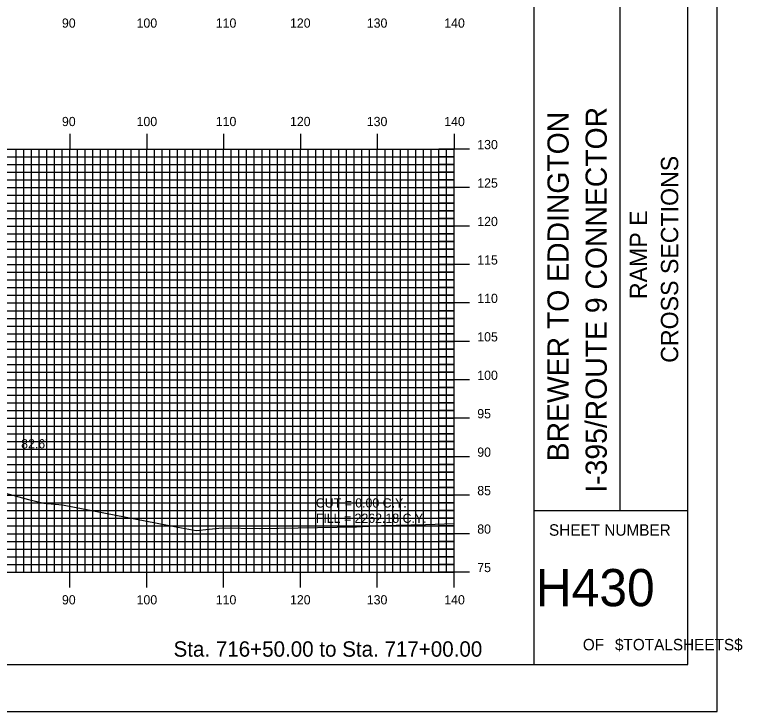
# Model space of a CAD drawing. Extents: x 856871 to 857214, y 364366 to 364586.
# Drawn here: x 857119.6 to 857214.3, y 364365.7 to 364456.3 of the extents above; entities that cross this region are included whole.
import ezdxf

# ---------------------------------------------------------------- set-up
doc = ezdxf.new("R2010")
doc.units = 0
for name, color, linetype in [('BORDER', 7, 'Continuous'), ('D_Text_Standard', 7, 'Continuous'), ('H_V ANNOTATION', 7, 'Continuous'), ('MAJOR', 7, 'Continuous'), ('MINOR', 7, 'Continuous'), ('PLOT BOUNDARY', 7, 'Continuous'), ('S_Roadway_Centerline', 7, 'Continuous')]:
    doc.layers.add(name, color=color, linetype=linetype)

msp = doc.modelspace()

# ---------------------------------------------------------------- linework, layer by layer
at = {"layer": 'BORDER'}
for p, q in [((857187.222, 364371.787), (857187.222, 364581.787)), ((857198.404, 364391.793), (857198.404, 364461.793)), ((857187.222, 364391.793), (857207.222, 364391.793))]:
    msp.add_line(p, q, dxfattribs=at)
msp.add_lwpolyline([(856887.222, 364371.787), (857207.222, 364371.787), (857207.222, 364581.787), (856887.222, 364581.787)], close=True, dxfattribs=at)
at = {"layer": 'MAJOR'}
for p, q in [((857126.822, 364440.791), (857126.822, 364438.787)), ((857136.822, 364440.791), (857136.822, 364438.787)), ((857146.822, 364440.791), (857146.822, 364438.787)), ((857156.822, 364440.791), (857156.822, 364438.787)), ((857166.822, 364440.791), (857166.822, 364438.787)), ((857176.822, 364440.791), (857176.822, 364438.787)), ((856896.822, 364438.787), (857176.822, 364438.787)), ((856896.822, 364438.787), (857176.822, 364438.787)), ((857126.822, 364383.787), (857126.822, 364438.787)), ((857136.822, 364383.787), (857136.822, 364438.787)), ((857146.822, 364383.787), (857146.822, 364438.787)), ((857156.822, 364383.787), (857156.822, 364438.787)), ((857166.822, 364383.787), (857166.822, 364438.787)), ((857178.826, 364438.787), (857174.818, 364438.787)), ((857176.822, 364383.787), (857176.822, 364438.787)), ((857176.822, 364383.787), (857176.822, 364438.787)), ((856896.822, 364433.787), (857176.822, 364433.787)), ((857178.826, 364433.787), (857174.818, 364433.787)), ((856896.822, 364428.787), (857176.822, 364428.787)), ((857178.826, 364428.787), (857174.818, 364428.787)), ((856896.822, 364423.787), (857176.822, 364423.787)), ((857178.826, 364423.787), (857174.818, 364423.787)), ((856896.822, 364418.787), (857176.822, 364418.787)), ((857178.826, 364418.787), (857174.818, 364418.787)), ((856896.822, 364413.787), (857176.822, 364413.787)), ((857178.826, 364413.787), (857174.818, 364413.787)), ((856896.822, 364408.787), (857176.822, 364408.787)), ((857178.826, 364408.787), (857174.818, 364408.787)), ((856896.822, 364403.787), (857176.822, 364403.787)), ((857178.826, 364403.787), (857174.818, 364403.787)), ((856896.822, 364398.787), (857176.822, 364398.787)), ((857178.826, 364398.787), (857174.818, 364398.787)), ((856896.822, 364393.787), (857176.822, 364393.787)), ((857178.826, 364393.787), (857174.818, 364393.787)), ((856896.822, 364388.787), (857176.822, 364388.787)), ((857178.826, 364388.787), (857174.818, 364388.787)), ((856896.822, 364383.787), (857176.822, 364383.787)), ((856896.822, 364383.787), (857176.822, 364383.787)), ((857126.822, 364381.783), (857126.822, 364383.787)), ((857136.822, 364381.783), (857136.822, 364383.787)), ((857146.822, 364381.783), (857146.822, 364383.787)), ((857156.822, 364381.783), (857156.822, 364383.787)), ((857166.822, 364381.783), (857166.822, 364383.787)), ((857178.826, 364383.787), (857174.818, 364383.787)), ((857176.822, 364381.783), (857176.822, 364383.787))]:
    msp.add_line(p, q, dxfattribs=at)
at = {"layer": 'MINOR'}
for p, q in [((857119.822, 364383.787), (857119.822, 364438.787)), ((857120.822, 364383.787), (857120.822, 364438.787)), ((857121.822, 364383.787), (857121.822, 364438.787)), ((857122.822, 364383.787), (857122.822, 364438.787)), ((857123.822, 364383.787), (857123.822, 364438.787)), ((857124.822, 364383.787), (857124.822, 364438.787)), ((857125.822, 364383.787), (857125.822, 364438.787)), ((857127.822, 364383.787), (857127.822, 364438.787)), ((857128.822, 364383.787), (857128.822, 364438.787)), ((857129.822, 364383.787), (857129.822, 364438.787)), ((857130.822, 364383.787), (857130.822, 364438.787)), ((857131.822, 364383.787), (857131.822, 364438.787)), ((857132.822, 364383.787), (857132.822, 364438.787)), ((857133.822, 364383.787), (857133.822, 364438.787)), ((857134.822, 364383.787), (857134.822, 364438.787)), ((857135.822, 364383.787), (857135.822, 364438.787)), ((857137.822, 364383.787), (857137.822, 364438.787)), ((857138.822, 364383.787), (857138.822, 364438.787)), ((857139.822, 364383.787), (857139.822, 364438.787)), ((857140.822, 364383.787), (857140.822, 364438.787)), ((857141.822, 364383.787), (857141.822, 364438.787)), ((857142.822, 364383.787), (857142.822, 364438.787)), ((857143.822, 364383.787), (857143.822, 364438.787)), ((857144.822, 364383.787), (857144.822, 364438.787)), ((857145.822, 364383.787), (857145.822, 364438.787)), ((857147.822, 364383.787), (857147.822, 364438.787)), ((857148.822, 364383.787), (857148.822, 364438.787)), ((857149.822, 364383.787), (857149.822, 364438.787)), ((857150.822, 364383.787), (857150.822, 364438.787)), ((857151.822, 364383.787), (857151.822, 364438.787)), ((857152.822, 364383.787), (857152.822, 364438.787)), ((857153.822, 364383.787), (857153.822, 364438.787)), ((857154.822, 364383.787), (857154.822, 364438.787)), ((857155.822, 364383.787), (857155.822, 364438.787)), ((857157.822, 364383.787), (857157.822, 364438.787)), ((857158.822, 364383.787), (857158.822, 364438.787)), ((857159.822, 364383.787), (857159.822, 364438.787)), ((857160.822, 364383.787), (857160.822, 364438.787)), ((857161.822, 364383.787), (857161.822, 364438.787)), ((857162.822, 364383.787), (857162.822, 364438.787)), ((857163.822, 364383.787), (857163.822, 364438.787)), ((857164.822, 364383.787), (857164.822, 364438.787)), ((857165.822, 364383.787), (857165.822, 364438.787)), ((857167.822, 364383.787), (857167.822, 364438.787)), ((857168.822, 364383.787), (857168.822, 364438.787)), ((857169.822, 364383.787), (857169.822, 364438.787)), ((857170.822, 364383.787), (857170.822, 364438.787)), ((857171.822, 364383.787), (857171.822, 364438.787)), ((857172.822, 364383.787), (857172.822, 364438.787)), ((857173.822, 364383.787), (857173.822, 364438.787)), ((857174.822, 364383.787), (857174.822, 364438.787)), ((857175.822, 364383.787), (857175.822, 364438.787)), ((856896.822, 364437.787), (857176.822, 364437.787)), ((857176.822, 364437.787), (857174.818, 364437.787)), ((856896.822, 364436.787), (857176.822, 364436.787)), ((857176.822, 364436.787), (857174.818, 364436.787)), ((856896.822, 364435.787), (857176.822, 364435.787)), ((857176.822, 364435.787), (857174.818, 364435.787)), ((856896.822, 364434.787), (857176.822, 364434.787)), ((857176.822, 364434.787), (857174.818, 364434.787)), ((856896.822, 364432.787), (857176.822, 364432.787)), ((857176.822, 364432.787), (857174.818, 364432.787)), ((856896.822, 364431.787), (857176.822, 364431.787)), ((857176.822, 364431.787), (857174.818, 364431.787)), ((856896.822, 364430.787), (857176.822, 364430.787)), ((857176.822, 364430.787), (857174.818, 364430.787)), ((856896.822, 364429.787), (857176.822, 364429.787)), ((857176.822, 364429.787), (857174.818, 364429.787)), ((856896.822, 364427.787), (857176.822, 364427.787)), ((857176.822, 364427.787), (857174.818, 364427.787)), ((856896.822, 364426.787), (857176.822, 364426.787)), ((857176.822, 364426.787), (857174.818, 364426.787)), ((856896.822, 364425.787), (857176.822, 364425.787)), ((857176.822, 364425.787), (857174.818, 364425.787)), ((856896.822, 364424.787), (857176.822, 364424.787)), ((857176.822, 364424.787), (857174.818, 364424.787)), ((856896.822, 364422.787), (857176.822, 364422.787)), ((857176.822, 364422.787), (857174.818, 364422.787)), ((856896.822, 364421.787), (857176.822, 364421.787)), ((857176.822, 364421.787), (857174.818, 364421.787)), ((856896.822, 364420.787), (857176.822, 364420.787)), ((857176.822, 364420.787), (857174.818, 364420.787)), ((856896.822, 364419.787), (857176.822, 364419.787)), ((857176.822, 364419.787), (857174.818, 364419.787)), ((856896.822, 364417.787), (857176.822, 364417.787)), ((857176.822, 364417.787), (857174.818, 364417.787)), ((856896.822, 364416.787), (857176.822, 364416.787)), ((857176.822, 364416.787), (857174.818, 364416.787)), ((856896.822, 364415.787), (857176.822, 364415.787)), ((857176.822, 364415.787), (857174.818, 364415.787)), ((856896.822, 364414.787), (857176.822, 364414.787)), ((857176.822, 364414.787), (857174.818, 364414.787)), ((856896.822, 364412.787), (857176.822, 364412.787)), ((857176.822, 364412.787), (857174.818, 364412.787)), ((856896.822, 364411.787), (857176.822, 364411.787)), ((857176.822, 364411.787), (857174.818, 364411.787)), ((856896.822, 364410.787), (857176.822, 364410.787)), ((857176.822, 364410.787), (857174.818, 364410.787)), ((856896.822, 364409.787), (857176.822, 364409.787)), ((857176.822, 364409.787), (857174.818, 364409.787)), ((856896.822, 364407.787), (857176.822, 364407.787)), ((857176.822, 364407.787), (857174.818, 364407.787)), ((856896.822, 364406.787), (857176.822, 364406.787)), ((857176.822, 364406.787), (857174.818, 364406.787)), ((856896.822, 364405.787), (857176.822, 364405.787)), ((857176.822, 364405.787), (857174.818, 364405.787)), ((856896.822, 364404.787), (857176.822, 364404.787)), ((857176.822, 364404.787), (857174.818, 364404.787)), ((856896.822, 364402.787), (857176.822, 364402.787)), ((857176.822, 364402.787), (857174.818, 364402.787)), ((856896.822, 364401.787), (857176.822, 364401.787)), ((857176.822, 364401.787), (857174.818, 364401.787)), ((856896.822, 364400.787), (857176.822, 364400.787)), ((857176.822, 364400.787), (857174.818, 364400.787)), ((856896.822, 364399.787), (857176.822, 364399.787)), ((857176.822, 364399.787), (857174.818, 364399.787)), ((856896.822, 364397.787), (857176.822, 364397.787)), ((857176.822, 364397.787), (857174.818, 364397.787)), ((856896.822, 364396.787), (857176.822, 364396.787)), ((857176.822, 364396.787), (857174.818, 364396.787)), ((856896.822, 364395.787), (857176.822, 364395.787)), ((857176.822, 364395.787), (857174.818, 364395.787)), ((856896.822, 364394.787), (857176.822, 364394.787)), ((857176.822, 364394.787), (857174.818, 364394.787)), ((856896.822, 364392.787), (857176.822, 364392.787)), ((857176.822, 364392.787), (857174.818, 364392.787)), ((856896.822, 364391.787), (857176.822, 364391.787)), ((857176.822, 364391.787), (857174.818, 364391.787)), ((856896.822, 364390.787), (857176.822, 364390.787)), ((857176.822, 364390.787), (857174.818, 364390.787)), ((856896.822, 364389.787), (857176.822, 364389.787)), ((857176.822, 364389.787), (857174.818, 364389.787)), ((856896.822, 364387.787), (857176.822, 364387.787)), ((857176.822, 364387.787), (857174.818, 364387.787)), ((856896.822, 364386.787), (857176.822, 364386.787)), ((857176.822, 364386.787), (857174.818, 364386.787)), ((856896.822, 364385.787), (857176.822, 364385.787)), ((857176.822, 364385.787), (857174.818, 364385.787)), ((856896.822, 364384.787), (857176.822, 364384.787)), ((857176.822, 364384.787), (857174.818, 364384.787))]:
    msp.add_line(p, q, dxfattribs=at)
at = {"layer": 'PLOT BOUNDARY'}
msp.add_lwpolyline([(856871.036, 364365.669), (857211.036, 364365.669), (857211.036, 364585.669), (856871.036, 364585.669)], close=True, dxfattribs=at)
at = {"layer": 'S_Roadway_Centerline'}
msp.add_lwpolyline([(857106.942, 364397.237), (857121.465, 364393.241), (857123.427, 364392.743), (857125.857, 364392.539), (857140.867, 364389.629), (857143.239, 364389.208), (857146.657, 364389.551), (857151.443, 364389.475), (857164.124, 364389.672), (857167.358, 364389.848), (857173.073, 364389.969), (857176.822, 364390.126)], dxfattribs=at)

# ---------------------------------------------------------------- texts
at = {"layer": 'BORDER'}
for s, height, p in [('BREWER TO EDDINGTON', 2.75575, (857191.711, 364398.196)), ('I-395/ROUTE 9 CONNECTOR', 2.75575, (857196.671, 364394.117)), ('CROSS SECTIONS', 2.25, (857205.964, 364411.009)), ('RAMP E', 2.25, (857201.914, 364419.291))]:
    msp.add_text(s, height=height, rotation=90, dxfattribs=at).set_placement(p)
for s, height, p in [('SHEET NUMBER', 1.49054, (857189.153, 364388.52)), ('H430', 4.8388, (857187.433, 364379.352)), ('$TOTALSHEETS$', 1.49054, (857197.735, 364373.613)), ('OF', 1.4905, (857193.556, 364373.613))]:
    msp.add_text(s, height=height, dxfattribs=at).set_placement(p)
at = {"layer": 'D_Text_Standard'}
for s, p in [("82.6'", (857120.489, 364399.874)), ('CUT = 0.00 C.Y.', (857158.822, 364392.187)), ('FILL = 2262.18 C.Y.', (857158.822, 364390.195))]:
    msp.add_text(s, height=1.2, dxfattribs=at).set_placement(p)
at = {"layer": 'H_V ANNOTATION'}
for s, height, p in [('90', 1.2, (857125.795, 364454.587)), ('100', 1.2, (857135.506, 364454.587)), ('110', 1.2, (857145.806, 364454.587)), ('120', 1.2, (857155.463, 364454.587)), ('130', 1.2, (857165.452, 364454.587)), ('140', 1.2, (857175.527, 364454.587)), ('90', 1.2, (857125.795, 364441.787)), ('100', 1.2, (857135.506, 364441.787)), ('110', 1.2, (857145.806, 364441.787)), ('120', 1.2, (857155.463, 364441.787)), ('130', 1.2, (857165.452, 364441.787)), ('140', 1.2, (857175.527, 364441.787)), ('130', 1.2, (857179.822, 364438.787)), ('125', 1.2, (857179.822, 364433.787)), ('120', 1.2, (857179.822, 364428.787)), ('115', 1.2, (857179.822, 364423.787)), ('110', 1.2, (857179.822, 364418.787)), ('105', 1.2, (857179.822, 364413.787)), ('100', 1.2, (857179.822, 364408.787)), ('95', 1.2, (857179.822, 364403.787)), ('90', 1.2, (857179.822, 364398.787)), ('85', 1.2, (857179.822, 364393.787)), ('80', 1.2, (857179.822, 364388.787)), ('75', 1.2, (857179.822, 364383.787)), ('90', 1.2, (857125.795, 364379.587)), ('100', 1.2, (857135.506, 364379.587)), ('110', 1.2, (857145.806, 364379.587)), ('120', 1.2, (857155.463, 364379.587)), ('130', 1.2, (857165.452, 364379.587)), ('140', 1.2, (857175.527, 364379.587)), ('Sta. 716+50.00 to Sta. 717+00.00', 2.0004, (857140.314, 364372.787))]:
    msp.add_text(s, height=height, dxfattribs=at).set_placement(p)

doc.saveas('drawing.dxf')
